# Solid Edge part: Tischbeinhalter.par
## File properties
Author: heha
Template: Normal.par
Last saved by: heha
Revision: 7
Application: Solid Edge
Genauigkeit: 0,99
Teilflächenrmatvorlage: Model Default
Coef. of Thermal Exp: 0.0
Thermal Conductivity: 0.0
Specific Heat: 0.0
Modulus of Elasticity: 0.0
Poission's Ratio: 0.0
Yield Stress: 0.0
Ultimate Stress: 0.0
Elongation: 0.0
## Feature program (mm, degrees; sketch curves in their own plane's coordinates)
sketch for "unnamed Protrusion 1" plane through (0, 0, 0) normal (1, 0, 0) x-axis (0, 1, 0)
  line (-25, 25) -> (25, 25)
  line (25, 25) -> (25, -25)
  line (25, -25) -> (-25, -25)
  line (-25, -25) -> (-25, 25)
  dimension (linear) = 25
extrude "unnamed Protrusion 1" add finite 25 along +normal
sketch for "unnamed Cutout 1" plane through (15, 0, 25) normal (0, 0, 1) x-axis (0, 1, 0)
  line (-8, 8) -> (8, 8)
  arc centre (9.1021, 13.8979) radius 6 from (8, 8) to (15, 15) ccw
  line (15, 15) -> (-15, 15)
  arc centre (-9.1021, 13.8979) radius 6 from (-15, 15) to (-8, 8) ccw
  dimension (linear) = 15
extrude "unnamed Cutout 1" cut through along -normal
sketch for "Diagonal1_Plane" plane through (15, -17.8952, -30.9953) normal (0, -0.5, -0.866025) x-axis (1, 0, 0)
  hole centre (0, 0) bore radius 5
hole "Diagonal1_Plane" diameter 10 through  FractionOfCurve = 0
sketch for "Diagonal2_Plane" plane through (15, 17.8952, -30.9953) normal (0, 0.5, -0.866025) x-axis (1, 0, 0)
  hole centre (0, 0) bore radius 5
hole "Diagonal2_Plane" diameter 10 through  FractionOfCurve = 0
sketch for "Bohrung_4" plane through (25, 0, 0) normal (1, 0, 0) x-axis (0, 1, 0)
  hole centre (18, 0) bore radius 2.5
hole "Bohrung_4" through  CounterBoreDepth = 5 mm
sketch for "unnamed Hole 1" plane through (25, 0, 0) normal (1, 0, 0) x-axis (0, 1, 0)
  hole centre (-18, 0) bore radius 2.5
hole "unnamed Hole 1" through
holes "Befestigung" diameter 5: "Bohrung_4", "unnamed Hole 1"
sketch for "unnamed Cutout 2" plane through (15, 0, 25) normal (0, 0, 1) x-axis (-1, 0, 0)
  line (-1, 24) -> (1, 24)
  line (1, 24) -> (1, -24)
  line (1, -24) -> (-1, -24)
  line (-1, -24) -> (-1, 24)
extrude "unnamed Cutout 2" cut through along -normal
fillet "Verrundungen" radius 2
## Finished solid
Body 1: solid body, 60 faces, 144 edges, 80 vertices.
  Faces by surface: cylinder 30, plane 22, sphere 8
  Edges by curve: line 76, circle 48, ellipse 16, intersection 4
Bounding box of the edges (mm; curved faces can reach further): 25.000 x 50.000 x 50.000, from (0, -25, -25) to (25, 25, 25).
Cylindrical faces by radius (mm): R2 x14, R2.5 x4, R5 x10, R6 x2
Spherical faces by radius (mm): R2 x8
Planar faces by outward normal: +x 7, +y 2, +z 2, -x 7, -y 2, -z 2
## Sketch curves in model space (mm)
line (15, 0, 0) -> (15, 17.8952, -30.9953)
line (15, 0, 0) -> (15, -17.8952, -30.9953)
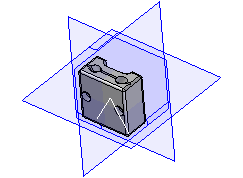
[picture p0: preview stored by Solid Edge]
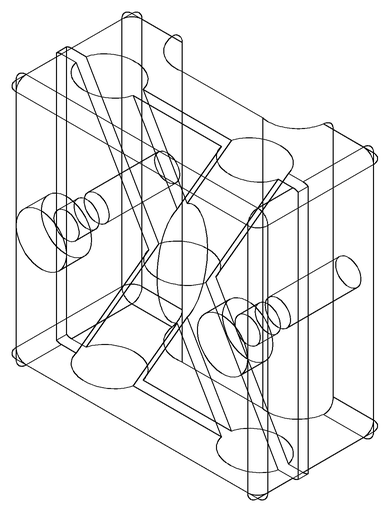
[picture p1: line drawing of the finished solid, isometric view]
